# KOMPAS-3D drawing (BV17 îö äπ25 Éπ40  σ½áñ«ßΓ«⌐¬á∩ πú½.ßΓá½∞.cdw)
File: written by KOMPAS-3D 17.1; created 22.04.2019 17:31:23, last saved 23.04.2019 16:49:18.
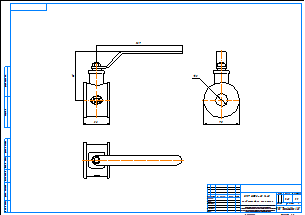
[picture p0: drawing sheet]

Sheet 1: A2, landscape

Title block, sheet 1: name: BV17 МФ Ду25 Ру40 / хладостойкая угл.сталь; material: Внимание! Данный продукт является объектом авторского права ООО «Торговый Дом АДЛ». / Запрещается изменение, копирование, распространение / (в том числе путем копирования на другие сайты и ресурсы в Интернете) / или любое иное использование информации и объектов без предварительного / согласия правообладателя (ООО «Торговый Дом АДЛ»).; mass: 1,41; sheets: 1; organisation: ООО "Торговый дом АДЛ"; sheet format: A2; stored path: \\adlc.lan\data\АДЛ_ПКД\3D-модели\ADL production\Краны шаровые серии BV\BV17 МФ хладостойкая угл.сталь Ру40\KOMPAS 2D\BV17 МФ Ду25 Ру40  хладостойкая угл.сталь.cdw

Views: Вид 1, Проекционный вид 2, Проекционный вид 3
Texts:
  user
Dimensions and other numbers on the sheet: 167; 95; 52; 70; 25; 1:1; 1; 1,41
